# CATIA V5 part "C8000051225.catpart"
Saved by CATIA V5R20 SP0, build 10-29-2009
Part number: C8000051225
Source: Unknown
Property "A": "30"
Property "ARTICLENO": "C8000051225"
Property "B": "13"
Property "BOMINFO": "C8000051225"
Property "C": "46"
Property "CA": "C8000051225"
Property "D1": "38"
Property "DES": "ROTATING EYEBOLT WITH RING Ton 0,5 M12x25"
Property "E": "50"
Property "H": "105"
Property "L": "25"
Property "LINA": "C8000051225"
Property "NB": "C8000051225"
Property "NBSYN": "$CODE."
Property "NN": "C800"
Property "NT": "Rotating eyebolt with ring"
Property "SIZE": "M12"
Property "SUPPLIER": "CF"
Property "SW": "30"
Property "WEIGHT": "500"
Property "WLL": "0.50"
Bounding box of the stored display mesh (mm): x -27.837 to 28, y -25 to 117.837, z -19 to 19
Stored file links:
  C:\Users\Utente\Desktop\3D files 800\C8000051225.catpart
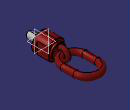
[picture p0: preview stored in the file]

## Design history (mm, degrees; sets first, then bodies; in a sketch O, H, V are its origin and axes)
Body1 "Geometry.1" (main body)
  Solid1 "C8000051225.catpart": solid without history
